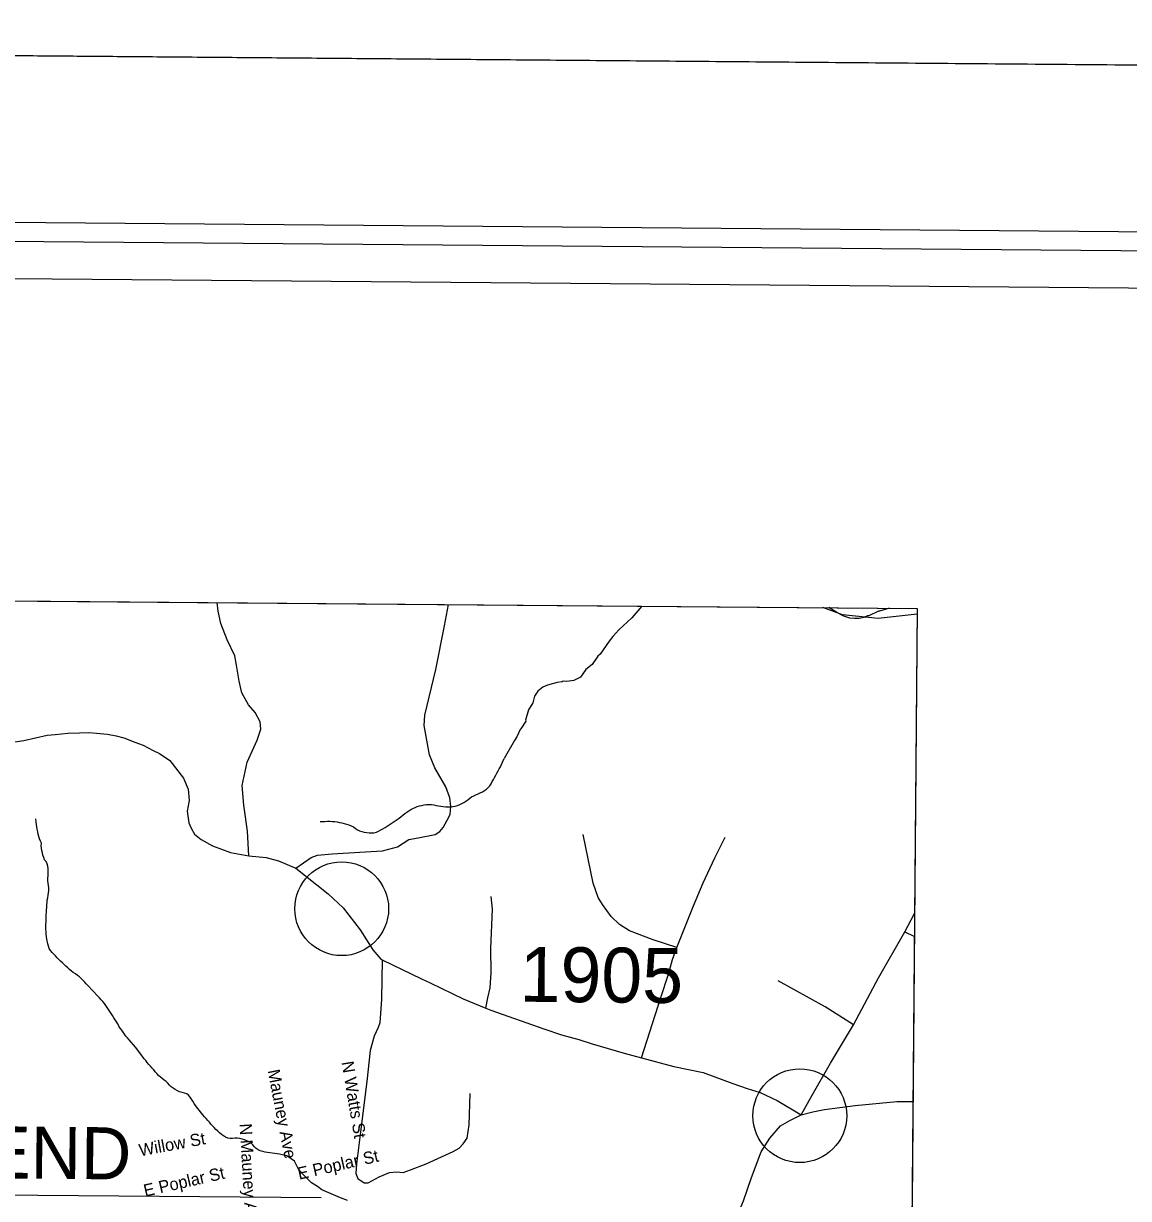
# Model space of a CAD drawing. Extents: x 1379453 to 1387082, y 594364 to 596664.
# Drawn here: x 1380505.6 to 1380802.6, y 596276.1 to 596592.1 of the extents above; entities that cross this region are included whole.
import ezdxf

# ---------------------------------------------------------------- set-up
doc = ezdxf.new("R2010")
doc.units = 0
for name, color, linetype in [('Old_Level_1', 7, 'Continuous'), ('Old_Level_10', 7, 'Continuous'), ('Old_Level_11', 7, 'Continuous'), ('Old_Level_32', 7, 'Continuous'), ('Old_Level_35', 7, 'Continuous'), ('Old_Level_59', 7, 'Continuous'), ('Old_Level_62', 7, 'Continuous'), ('Old_Level_8', 7, 'Continuous'), ('Sheet Clip Boundary CELL', 7, 'Continuous'), ('Sheet Cutting Line CELL', 7, 'Continuous'), ('Sheet Plot Border Inside CELL', 7, 'Continuous'), ('Sheet Plot Border Outside CELL', 7, 'Continuous'), ('Sheet Title CELL', 7, 'Continuous')]:
    doc.layers.add(name, color=color, linetype=linetype)

msp = doc.modelspace()

# ---------------------------------------------------------------- linework, layer by layer
at = {"layer": 'Old_Level_1'}
for p, q in [((1379993.85, 596441.11), (1380745.81, 596434.81)), ((1380745.81, 596434.81), (1380740.66, 595820.56))]:
    msp.add_line(p, q, dxfattribs=at)
at = {"layer": 'Old_Level_11'}
msp.add_line((1380490.3, 596277.16), (1380585.59, 596276.36), dxfattribs=at)
at = {"layer": 'Old_Level_32'}
for points in [[(1380566.13, 596368.24), (1380565.73, 596374.87), (1380564.82, 596381.89), (1380564.32, 596387.2), (1380565.68, 596393.44), (1380568.34, 596399.41), (1380569.33, 596402.29), (1380569.14, 596404.29), (1380567.85, 596406.77), (1380566.08, 596408.85), (1380564.25, 596412.1), (1380563.52, 596415.27), (1380562.8, 596419.54), (1380562.34, 596422.03), (1380560.32, 596426.38), (1380558.63, 596430.72), (1380557.91, 596434.03), (1380557.65, 596436.38)], [(1380501.4, 596398.68), (1380505.62, 596399.24), (1380511.92, 596400.72), (1380514.1, 596400.9), (1380517.43, 596401.29), (1380520.64, 596401.33), (1380523.14, 596401.45), (1380525.16, 596401.27), (1380528.09, 596400.97), (1380530.48, 596400.51), (1380532.55, 596400.02), (1380535.47, 596398.83), (1380537.75, 596398.01), (1380540.44, 596396.63), (1380542.09, 596395.79), (1380544.88, 596393.89), (1380548.55, 596389.16), (1380549.83, 596386.15), (1380550.06, 596383.11), (1380549.58, 596380.24), (1380549.97, 596377.11), (1380550.58, 596375.86), (1380551.5, 596374.08), (1380553.34, 596372.65), (1380556.32, 596370.94), (1380561.22, 596369.12), (1380566.13, 596368.24)], [(1380681.16, 596343.61), (1380674.81, 596345.63), (1380668.47, 596348.11), (1380665.78, 596349.82), (1380663.58, 596351.9), (1380661.2, 596355.19), (1380660.06, 596357.07), (1380658.74, 596360.92), (1380656.05, 596374.04)], [(1380681.16, 596343.61), (1380685.71, 596354.81), (1380688.29, 596361), (1380691.38, 596367.69), (1380694.15, 596373.31)], [(1380566.13, 596368.24), (1380570.76, 596367.83), (1380574.12, 596366.96), (1380578.74, 596364.95), (1380587.46, 596358.05), (1380591.47, 596354.28), (1380596.04, 596348.39), (1380599.49, 596343), (1380601.66, 596340.45), (1380602, 596340.26), (1380612.54, 596335.16), (1380614.86, 596334.13), (1380623.76, 596329.77), (1380629.84, 596327.26), (1380631.16, 596326.72), (1380645.4, 596321.69), (1380650.16, 596320.09), (1380654.86, 596318.82), (1380658.47, 596317.67), (1380667.05, 596315.17), (1380671.68, 596313.94)], [(1380742.48, 596347.83), (1380745.12, 596352.76)], [(1380714.63, 596298.61), (1380717.57, 596303.91), (1380722.53, 596312.52), (1380728.67, 596322.82), (1380735.43, 596335.48), (1380742.48, 596347.83)], [(1380742.48, 596347.83), (1380745.07, 596346.55)], [(1380671.68, 596313.94), (1380676.9, 596330.17), (1380678.98, 596336.42), (1380680.07, 596340.34), (1380681.16, 596343.61)], [(1380671.68, 596313.94), (1380680.39, 596311.61), (1380688.27, 596309.99), (1380696.28, 596306.99), (1380700.13, 596305.65), (1380703.59, 596304.59), (1380708.2, 596302.5), (1380714.63, 596298.61)], [(1380714.63, 596298.61), (1380717.72, 596299.42), (1380720.89, 596300.08), (1380729.16, 596301.11), (1380740.32, 596302.23), (1380744.7, 596302.23)], [(1380690.45, 596156.89), (1380692.15, 596160.17), (1380692.86, 596162.71), (1380693.47, 596165.59), (1380693.82, 596168.85), (1380692.68, 596179.21), (1380691.15, 596197.29), (1380689.28, 596213.3), (1380685.42, 596228.02), (1380684.56, 596232.6), (1380684.72, 596236.11), (1380685.33, 596239.56), (1380687.11, 596243.25), (1380688.77, 596249.19), (1380691.61, 596256.45), (1380697.2, 596271.02), (1380699.14, 596275.49), (1380701.23, 596281.75), (1380703.91, 596288.62), (1380706.19, 596292.32), (1380709.11, 596295.66), (1380711.61, 596297.12), (1380714.63, 596298.61)]]:
    msp.add_lwpolyline(points, dxfattribs=at)
for centre in [(1380591.1, 596354.03), (1380714.26, 596298.36)]:
    msp.add_circle(centre, 12.61, dxfattribs=at)
at = {"layer": 'Old_Level_35'}
for points in [[(1380578.74, 596364.95), (1380582.91, 596367.82), (1380584.55, 596368.46), (1380588.51, 596368.8), (1380597.48, 596369.38), (1380602.11, 596369.62), (1380606.07, 596370.71), (1380609.17, 596372.65), (1380611.69, 596373.1), (1380616.22, 596374), (1380617.49, 596374.83), (1380618.37, 596375.85), (1380619.44, 596377.81), (1380620.22, 596379.39), (1380620.44, 596381.54), (1380620.17, 596383.88), (1380619.08, 596386.86), (1380616.17, 596391.89), (1380614.72, 596395.43), (1380613.31, 596403.29), (1380613.45, 596406.13), (1380616.4, 596418.39), (1380618.76, 596430.08), (1380619.82, 596435.86)], [(1380629.84, 596327.26), (1380630.42, 596330.09), (1380631.02, 596332.8), (1380631.25, 596336.82), (1380631.2, 596343.37), (1380631.68, 596353.94), (1380631.32, 596357.31)], [(1380602, 596340.26), (1380601.78, 596329.68), (1380601.33, 596323.32), (1380600.94, 596322.11), (1380599.86, 596319.78), (1380598.77, 596315.86), (1380597.83, 596307.54), (1380596.17, 596293.99), (1380595.04, 596285.39), (1380594.92, 596282.86), (1380595.39, 596281.45), (1380597.12, 596280.32), (1380598.18, 596280.31), (1380601.18, 596281.97), (1380603.99, 596283.07), (1380605.82, 596283.24), (1380607.65, 596283.13), (1380609.59, 596283.77), (1380613.84, 596285.42), (1380621.11, 596288.72), (1380622.65, 596289.65), (1380623.73, 596290.76), (1380624.8, 596292.34), (1380625.41, 596295.89), (1380625.67, 596304.31)], [(1380728.67, 596322.82), (1380721.05, 596327.65), (1380708.47, 596334.68)]]:
    msp.add_lwpolyline(points, dxfattribs=at)
at = {"layer": 'Old_Level_59'}
msp.add_lwpolyline([(1380745.8, 596433.26), (1380735.37, 596432.13), (1380725.73, 596433.06), (1380720.46, 596435.02)], dxfattribs=at)
at = {"layer": 'Old_Level_62'}
for points in [[(1380671.81, 596435.43), (1380669.09, 596432.3), (1380665.64, 596429.05), (1380663.99, 596427.26), (1380662.99, 596426.01), (1380660.56, 596422.49), (1380659.99, 596421.95), (1380658.48, 596419.76), (1380656.77, 596418.37), (1380655.34, 596416.33), (1380653.55, 596415.43), (1380651.62, 596415.17), (1380650.66, 596415.2), (1380650.34, 596415.05), (1380649.06, 596414.92), (1380646.47, 596414.2), (1380645.17, 596413.61), (1380643.86, 596412.53), (1380642.94, 596411.2), (1380642.49, 596409.37), (1380641.31, 596407.49), (1380640.55, 596404.77), (1380640.58, 596404.47), (1380639.28, 596402.38), (1380639.08, 596402.28), (1380638.22, 596400.23), (1380637.55, 596399.29), (1380634.77, 596394.41)], [(1380738.41, 596434.87), (1380735.72, 596434.03), (1380735.4, 596434.04), (1380732.81, 596432.84), (1380732.49, 596432.85), (1380731.51, 596432.4), (1380730.22, 596432.12), (1380728.94, 596432.08), (1380727.67, 596432.2), (1380726.08, 596432.72), (1380724.19, 596433.74), (1380722.08, 596435.01)], [(1380585.27, 596377.52), (1380585.92, 596377.53), (1380586.58, 596377.54), (1380587.24, 596377.56), (1380587.9, 596377.56), (1380588.55, 596377.54), (1380589.21, 596377.49), (1380589.86, 596377.39), (1380590.5, 596377.26), (1380591.14, 596377.1), (1380591.78, 596376.94), (1380592.41, 596376.76), (1380593.04, 596376.56), (1380593.65, 596376.33), (1380594.24, 596376.04), (1380594.78, 596375.65), (1380595.31, 596375.26), (1380595.9, 596375), (1380596.53, 596374.82), (1380597.18, 596374.66), (1380597.84, 596374.53), (1380598.49, 596374.46), (1380599.15, 596374.43), (1380599.78, 596374.47), (1380600.41, 596374.65), (1380601.03, 596374.91), (1380601.62, 596375.22), (1380602.19, 596375.54), (1380602.75, 596375.88), (1380603.31, 596376.22), (1380603.86, 596376.58), (1380604.4, 596376.94), (1380604.95, 596377.31), (1380605.48, 596377.68), (1380606.02, 596378.06), (1380606.55, 596378.43), (1380607.05, 596378.83), (1380607.56, 596379.24), (1380608.06, 596379.65), (1380608.57, 596380.03), (1380609.12, 596380.39), (1380609.67, 596380.71), (1380610.25, 596381.01), (1380610.83, 596381.29), (1380611.43, 596381.51), (1380612.05, 596381.68), (1380612.67, 596381.83), (1380613.3, 596381.97), (1380613.93, 596382.07), (1380614.57, 596382.11), (1380615.22, 596382.05), (1380615.86, 596381.95), (1380616.49, 596381.81), (1380617.12, 596381.69), (1380617.76, 596381.61), (1380618.41, 596381.54), (1380619.06, 596381.48), (1380619.71, 596381.44), (1380620.35, 596381.45), (1380620.97, 596381.52), (1380621.6, 596381.66), (1380622.22, 596381.84), (1380622.82, 596382.06), (1380623.41, 596382.31), (1380623.97, 596382.6), (1380624.5, 596382.95), (1380625.01, 596383.34), (1380625.52, 596383.74), (1380626.01, 596384.11), (1380626.59, 596384.38), (1380627.18, 596384.64), (1380627.77, 596384.9), (1380628.35, 596385.18), (1380628.92, 596385.49), (1380629.47, 596385.82), (1380630, 596386.2), (1380630.48, 596386.63), (1380630.91, 596387.12), (1380631.26, 596387.67), (1380631.58, 596388.23), (1380631.89, 596388.79), (1380632.21, 596389.36), (1380632.52, 596389.94), (1380632.83, 596390.51), (1380633.14, 596391.09), (1380633.45, 596391.67), (1380633.75, 596392.24), (1380634.06, 596392.82), (1380634.36, 596393.41), (1380634.77, 596394.41)], [(1380510.62, 596369.04), (1380510.49, 596369.69), (1380510.39, 596370.34), (1380510.32, 596370.99), (1380510.38, 596371.65), (1380510.16, 596372.25), (1380509.85, 596372.84), (1380509.66, 596373.47), (1380509.5, 596374.1), (1380509.37, 596374.75), (1380509.24, 596375.39), (1380509.12, 596376.04), (1380509.01, 596376.69), (1380508.92, 596377.34), (1380508.82, 596378.23)], [(1380543.39, 596307.96), (1380542.84, 596308.33), (1380542.34, 596308.75), (1380541.87, 596309.21), (1380541.42, 596309.69), (1380540.98, 596310.18), (1380540.55, 596310.67), (1380540.12, 596311.17), (1380539.68, 596311.67), (1380539.26, 596312.17), (1380538.84, 596312.67), (1380538.43, 596313.18), (1380538.02, 596313.69), (1380536.84, 596315.25), (1380535.68, 596316.84), (1380533.95, 596318.81), (1380533.5, 596319.29), (1380533.1, 596319.8), (1380532.7, 596320.32), (1380532.32, 596320.86), (1380531.95, 596321.4), (1380531.58, 596321.95), (1380531.22, 596322.49), (1380530.87, 596323.05), (1380530.52, 596323.6), (1380530.18, 596324.16), (1380529.83, 596324.73), (1380529.49, 596325.29), (1380529.15, 596325.85), (1380528.8, 596326.4), (1380528.44, 596326.95), (1380528.07, 596327.49), (1380527.69, 596328.03), (1380527.3, 596328.55), (1380526.89, 596329.06), (1380526.46, 596329.57), (1380526.02, 596330.05), (1380525.54, 596330.5), (1380522.83, 596333.36), (1380522.39, 596333.85), (1380521.94, 596334.33), (1380521.49, 596334.81), (1380521.03, 596335.27), (1380520.56, 596335.72), (1380520.04, 596336.12), (1380519.49, 596336.48), (1380518.94, 596336.85), (1380518.43, 596337.26), (1380517.94, 596337.7), (1380517.46, 596338.14), (1380516.97, 596338.59), (1380516.48, 596339.04), (1380516.01, 596339.49), (1380515.53, 596339.95), (1380515.05, 596340.4), (1380514.59, 596340.87), (1380514.13, 596341.34), (1380513.68, 596341.82), (1380513.25, 596342.3), (1380512.82, 596342.8), (1380512.49, 596343.35), (1380512.26, 596343.98), (1380512.06, 596344.62), (1380511.86, 596345.88), (1380511.76, 596346.53), (1380511.67, 596347.19), (1380511.61, 596347.84), (1380511.57, 596348.5), (1380511.57, 596349.15), (1380511.58, 596349.81), (1380511.6, 596350.46), (1380511.62, 596351.12), (1380511.64, 596351.78), (1380511.68, 596352.43), (1380511.71, 596353.09), (1380511.75, 596353.74), (1380511.79, 596354.4), (1380511.83, 596355.05), (1380511.87, 596355.71), (1380511.91, 596356.36), (1380512.09, 596356.99), (1380512.18, 596357.64), (1380512.26, 596358.3), (1380512.32, 596358.95), (1380512.33, 596359.61), (1380512.27, 596360.26), (1380512.18, 596360.91), (1380512.11, 596361.56), (1380512.1, 596362.22), (1380512.14, 596362.88), (1380512.19, 596363.54), (1380512.22, 596364.2), (1380512.22, 596364.85), (1380512.11, 596365.49), (1380511.9, 596366.13), (1380511.65, 596366.73), (1380511.21, 596367.17), (1380510.98, 596367.78), (1380510.77, 596368.4), (1380510.62, 596369.04)], [(1380592.64, 596275.6), (1380590.8, 596276.31), (1380585.73, 596278.44), (1380584.58, 596279.37), (1380582.97, 596280.31), (1380581.36, 596281.95), (1380579.53, 596283.81), (1380578.39, 596286.14), (1380576.32, 596287.55), (1380574.39, 596288.04), (1380573.74, 596288.09), (1380573.08, 596288.17), (1380572.43, 596288.27), (1380571.79, 596288.36), (1380571.14, 596288.48), (1380570.49, 596288.6), (1380569.85, 596288.75), (1380569.22, 596288.94), (1380568.6, 596289.19), (1380568.06, 596289.54), (1380567.62, 596290.03), (1380567.21, 596290.57), (1380566.75, 596291.02), (1380566.19, 596291.35), (1380565.6, 596291.63), (1380564.98, 596291.89), (1380564.35, 596292.1), (1380563.71, 596292.27), (1380563.08, 596292.36), (1380562.42, 596292.32), (1380561.76, 596292.25), (1380561.1, 596292.24), (1380560.45, 596292.37), (1380559.85, 596292.63), (1380559.29, 596292.98), (1380558.74, 596293.35), (1380558.23, 596293.75), (1380557.76, 596294.21), (1380557.3, 596294.68), (1380556.85, 596295.16), (1380556.4, 596295.63), (1380555.95, 596296.12), (1380555.51, 596296.6), (1380555.07, 596297.09), (1380554.63, 596297.58), (1380554.19, 596298.07), (1380553.77, 596298.57), (1380553.36, 596299.08), (1380551.77, 596301.13), (1380551.39, 596301.67), (1380551.05, 596302.25), (1380550.72, 596302.84), (1380550.37, 596303.39), (1380549.95, 596303.87), (1380549.43, 596304.23), (1380548.83, 596304.47), (1380548.18, 596304.65), (1380547.53, 596304.83), (1380546.91, 596305.08), (1380546.35, 596305.4), (1380545.8, 596305.77), (1380545.27, 596306.17), (1380544.77, 596306.59), (1380544.39, 596307.13), (1380543.93, 596307.59), (1380543.39, 596307.96)]]:
    msp.add_lwpolyline(points, dxfattribs=at)
at = {"layer": 'Sheet Clip Boundary CELL'}
msp.add_lwpolyline([(1379993.85, 596441.11), (1380745.81, 596434.81), (1380742.6, 596052.18), (1380696.17, 596052.63), (1380694.49, 595820.94), (1379988.71, 595826.86)], close=True, dxfattribs=at)
at = {"layer": 'Sheet Cutting Line CELL'}
msp.add_line((1379471.02, 596592.12), (1382838.9, 596563.91), dxfattribs=at)
at = {"layer": 'Sheet Plot Border Inside CELL'}
msp.add_lwpolyline([(1379478.96, 594436.88), (1382811.85, 594408.96), (1382829.53, 596519.08), (1379496.64, 596547.01)], close=True, dxfattribs=at)
at = {"layer": 'Sheet Plot Border Outside CELL'}
msp.add_lwpolyline([(1382838.9, 596563.91), (1379471.02, 596592.12), (1379452.59, 594392.22), (1382820.47, 594364.01)], close=True, dxfattribs=at)
at = {"layer": 'Sheet Title CELL'}
for points in [[(1382784.51, 596514.36), (1379824.56, 596539.18)], [(1382774.4, 596504.45), (1379934.53, 596528.24)]]:
    msp.add_lwpolyline(points, dxfattribs=at)

# ---------------------------------------------------------------- texts
at = {"layer": 'Old_Level_10'}
for s, height, rotation, p in [('Mauney Ave', 3.281, 281, (1380571.16, 596310.5)), ('N Watts St', 3.281, 279.58, (1380591.03, 596312.76)), ('N Mauney Ave', 3.2808, 273.3637, (1380563.63, 596296.2)), ('Willow St', 3.281, 10.566, (1380536.93, 596287.43)), ('E Poplar St', 3.2808, 12.8732, (1380579.65, 596281.14)), ('E Poplar St', 3.2808, 12.8599, (1380538.25, 596276.56))]:
    msp.add_text(s, height=height, rotation=rotation, dxfattribs=at).set_placement(p)
at = {"layer": 'Old_Level_11'}
msp.add_text('END', height=14, rotation=359.52, dxfattribs=at).set_placement((1380494.94, 596281.54))
at = {"layer": 'Old_Level_8'}
msp.add_text('1905', height=14.764, rotation=359.52, dxfattribs=at).set_placement((1380638.9, 596329.03))

doc.saveas('drawing.dxf')
